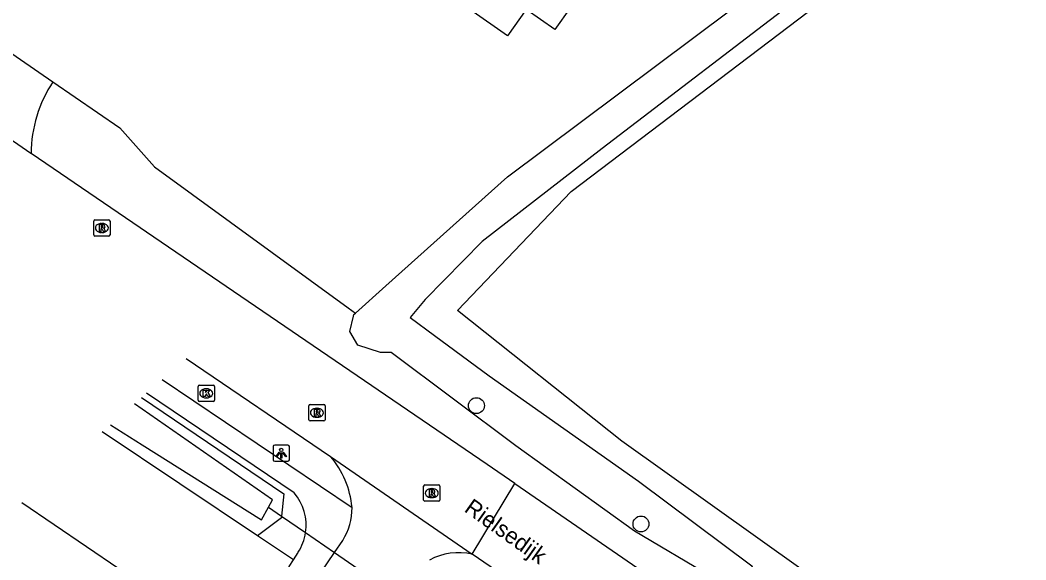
# Model space of a CAD drawing. Extents: x 163863 to 164644, y 379566 to 382155.
# Drawn here: x 164174.8 to 164236.6, y 381853.4 to 381886.6 of the extents above; entities that cross this region are included whole.
import ezdxf

# ---------------------------------------------------------------- set-up
doc = ezdxf.new("R2010")
doc.units = 0
for name, color, linetype in [('IMGEO_Boom', 7, 'Continuous'), ('IMGEO_Duiker', 7, 'Continuous'), ('IMGEO_Erf', 7, 'Continuous'), ('IMGEO_Grasland_overig', 7, 'Continuous'), ('IMGEO_Groenvoorziening', 7, 'Continuous'), ('IMGEO_Kolk', 7, 'Continuous'), ('IMGEO_Lichtpunt', 7, 'Continuous'), ('IMGEO_Openbare_ruimte_label', 7, 'Continuous'), ('IMGEO_Pand', 7, 'Continuous'), ('IMGEO_Rijbaan_lokaal_gesloten', 7, 'Continuous'), ('IMGEO_Rijbaan_lokaal_open', 7, 'Continuous'), ('IMGEO_Rioolput', 7, 'Continuous'), ('IMGEO_Voetpad_open', 7, 'Continuous'), ('IMGEO_Waterloop', 7, 'Continuous')]:
    doc.layers.add(name, color=color, linetype=linetype)

msp = doc.modelspace()

# ---------------------------------------------------------------- linework, layer by layer
at = {"layer": 'IMGEO_Boom'}
for centre in [(164202.821, 381862.893), (164212.934, 381855.62)]:
    msp.add_circle(centre, 0.489, dxfattribs=at)
at = {"layer": 'IMGEO_Duiker'}
msp.add_lwpolyline([(164190.042, 381856.658), (164190.846, 381856.104), (164192.323, 381855.089), (164194.104, 381853.864), (164197.871, 381851.272), (164199.409, 381850.214), (164201.216, 381848.971), (164201.883, 381848.512)], dxfattribs=at)
at = {"layer": 'IMGEO_Erf'}
msp.add_lwpolyline([(164189.365, 381854.902), (164179.829, 381861.277)], dxfattribs=at)
at = {"layer": 'IMGEO_Grasland_overig'}
msp.add_lwpolyline([(164335.006, 381775.051), (164322.428, 381783.408), (164286.005, 381809.753), (164256.457, 381829.627), (164222.906, 381852.769), (164211.763, 381860.7), (164201.663, 381868.745), (164208.654, 381876.058), (164252.396, 381909.265)], dxfattribs=at)
at = {"layer": 'IMGEO_Groenvoorziening'}
for points in [[(164176.8, 381882.795), (164180.902, 381879.968), (164183.031, 381877.576), (164194.945, 381868.909), (164195.394, 381868.583)], [(164182.231, 381863.385), (164190.987, 381857.475), (164190.846, 381856.104), (164190.836, 381856.002), (164189.365, 381854.902)], [(164191.58, 381853.421), (164189.365, 381854.902)]]:
    msp.add_lwpolyline(points, dxfattribs=at)
at = {"layer": 'IMGEO_Kolk'}
for p, q in [((164185.719, 381863.221), (164185.719, 381864.073)), ((164185.794, 381864.147), (164186.646, 381864.147)), ((164186.72, 381864.073), (164186.72, 381863.221)), ((164186.23, 381863.367), (164186.205, 381863.367)), ((164186.207, 381863.927), (164186.232, 381863.927)), ((164186.646, 381863.147), (164185.794, 381863.147))]:
    msp.add_line(p, q, dxfattribs=at)
for points in [[(164185.719, 381863.221), (164185.719, 381864.073)], [(164185.794, 381864.147), (164186.646, 381864.147)], [(164186.72, 381864.073), (164186.72, 381863.221)], [(164186.04, 381863.847), (164186.163, 381863.847), (164186.163, 381863.696), (164186.293, 381863.847), (164186.457, 381863.847), (164186.311, 381863.696), (164186.464, 381863.447), (164186.312, 381863.447), (164186.227, 381863.611), (164186.163, 381863.544), (164186.163, 381863.447), (164186.04, 381863.447), (164186.04, 381863.847)], [(164186.646, 381863.147), (164185.794, 381863.147)]]:
    msp.add_lwpolyline(points, dxfattribs=at)
for centre, start, end in [((164185.796, 381864.071), 91.55205, 178.44795), ((164185.796, 381864.071), 91.55205, 178.44795), ((164186.644, 381864.071), 1.55205, 88.44795), ((164186.644, 381864.071), 1.55205, 88.44795), ((164185.796, 381863.223), 181.55205, 268.44795), ((164185.796, 381863.223), 181.55205, 268.44795), ((164186.644, 381863.223), 271.55205, 358.44795), ((164186.644, 381863.223), 271.55205, 358.44795)]:
    msp.add_arc(centre, 0.0765, start, end, dxfattribs=at)
for centre, major_axis, ratio, start_param, end_param in [((164186.206, 381863.647), (-0.387, 0.002), 0.722429, 4.712389, 7.853982), ((164186.231, 381863.647), (-0.39, 0.002), 0.717154, 1.570796, 4.712389)]:
    msp.add_ellipse(centre, major_axis=major_axis, ratio=ratio, start_param=start_param, end_param=end_param, dxfattribs=at)
at = {"layer": 'IMGEO_Lichtpunt'}
for p, q in [((164190.331, 381860.374), (164190.331, 381859.567)), ((164190.331, 381860.374), (164190.331, 381859.567)), ((164191.233, 381860.469), (164190.425, 381860.469)), ((164191.233, 381860.469), (164190.425, 381860.469)), ((164191.327, 381859.567), (164191.327, 381860.374)), ((164191.327, 381859.567), (164191.327, 381860.374)), ((164190.425, 381859.473), (164191.233, 381859.473)), ((164190.425, 381859.473), (164191.233, 381859.473))]:
    msp.add_line(p, q, dxfattribs=at)
for points in [[(164190.705, 381860.038), (164190.744, 381860.01), (164190.556, 381859.748), (164190.518, 381859.775), (164190.705, 381860.038)], [(164190.807, 381859.99), (164190.854, 381859.99), (164190.854, 381859.668), (164190.807, 381859.668), (164190.807, 381859.99)], [(164190.917, 381860.01), (164190.955, 381860.037), (164191.142, 381859.775), (164191.103, 381859.747), (164190.917, 381860.01)]]:
    msp.add_lwpolyline(points, dxfattribs=at)
msp.add_circle((164190.83, 381860.172), 0.0994, dxfattribs=at)
for centre, start, end in [((164190.425, 381860.374), 90, 180), ((164190.425, 381860.374), 90, 180), ((164191.233, 381860.374), 0, 90), ((164191.233, 381860.374), 0, 90), ((164190.425, 381859.567), 180, 270), ((164190.425, 381859.567), 180, 270), ((164191.233, 381859.567), 270, 0), ((164191.233, 381859.567), 270, 360)]:
    msp.add_arc(centre, 0.0946, start, end, dxfattribs=at)
at = {"layer": 'IMGEO_Pand'}
for points in [[(164212.28, 381892.593), (164210.522, 381890.091), (164207.647, 381886), (164205.881, 381887.241), (164204.735, 381885.611), (164198.195, 381890.205), (164199.337, 381891.829), (164194.385, 381895.308), (164197.26, 381899.4), (164199.022, 381901.908), (164201.324, 381900.291), (164203.411, 381898.824), (164212.28, 381892.593)], [(164174.878, 381856.933), (164182.827, 381851.535), (164178.088, 381844.548), (164177.173, 381845.157), (164173.526, 381839.8), (164167.892, 381843.609), (164171.538, 381849.002), (164168.319, 381851.178)]]:
    msp.add_lwpolyline(points, dxfattribs=at)
at = {"layer": 'IMGEO_Rijbaan_lokaal_gesloten'}
for points in [[(164175.458, 381878.387), (164175.446, 381878.395), (164166.649, 381884.443), (164166.499, 381884.544)], [(164205.181, 381858.114), (164203.483, 381859.285), (164175.458, 381878.387)], [(164184.975, 381865.791), (164193.85, 381859.772)], [(164193.85, 381859.772), (164202.562, 381853.773)], [(164202.562, 381853.773), (164205.181, 381858.114)], [(164205.181, 381858.114), (164214.31, 381851.815)], [(164213.948, 381845.959), (164202.562, 381853.773)]]:
    msp.add_lwpolyline(points, dxfattribs=at)
at = {"layer": 'IMGEO_Rijbaan_lokaal_open'}
msp.add_lwpolyline([(164192.817, 381851.959), (164194.104, 381853.864), (164194.609, 381854.612)], dxfattribs=at)
for centre, radius, start, end in [((164189.621, 381856.131), 5.58, 5.22966, 40.72522), ((164191.427, 381856.599), 3.752, 328.02444, 0.6303), ((164201.76, 381849.906), 3.949, 78.28872, 117.56243)]:
    msp.add_arc(centre, radius, start, end, dxfattribs=at)
at = {"layer": 'IMGEO_Rioolput'}
for p, q in [((164179.304, 381873.386), (164179.304, 381874.238)), ((164179.379, 381874.312), (164180.231, 381874.312)), ((164179.792, 381874.092), (164179.817, 381874.092)), ((164180.305, 381874.238), (164180.305, 381873.386)), ((164180.231, 381873.312), (164179.379, 381873.312)), ((164179.815, 381873.532), (164179.79, 381873.532)), ((164192.521, 381862.03), (164192.521, 381862.882)), ((164192.596, 381862.956), (164193.448, 381862.956)), ((164193.009, 381862.736), (164193.034, 381862.736)), ((164193.522, 381862.882), (164193.522, 381862.03)), ((164193.032, 381862.176), (164193.007, 381862.176)), ((164193.448, 381861.956), (164192.596, 381861.956)), ((164199.579, 381857.093), (164199.579, 381857.945)), ((164199.654, 381858.019), (164200.506, 381858.019)), ((164200.067, 381857.799), (164200.092, 381857.799)), ((164200.58, 381857.945), (164200.58, 381857.093)), ((164200.09, 381857.239), (164200.065, 381857.239)), ((164200.506, 381857.019), (164199.654, 381857.019))]:
    msp.add_line(p, q, dxfattribs=at)
for points in [[(164179.304, 381873.386), (164179.304, 381874.238)], [(164179.379, 381874.312), (164180.231, 381874.312)], [(164179.893, 381874.01), (164179.641, 381874.012), (164179.641, 381873.612)], [(164179.819, 381873.931), (164179.765, 381873.931), (164179.765, 381873.85)], [(164179.765, 381873.85), (164179.817, 381873.85)], [(164180.305, 381874.238), (164180.305, 381873.386)], [(164180.231, 381873.312), (164179.379, 381873.312)], [(164179.641, 381873.612), (164179.765, 381873.612), (164179.765, 381873.774), (164179.776, 381873.774)], [(164179.823, 381873.745), (164179.894, 381873.612), (164180.034, 381873.612), (164179.969, 381873.738)], [(164192.521, 381862.03), (164192.521, 381862.882)], [(164192.596, 381862.956), (164193.448, 381862.956)], [(164193.522, 381862.882), (164193.522, 381862.03)], [(164193.11, 381862.654), (164192.858, 381862.656), (164192.858, 381862.256)], [(164192.858, 381862.256), (164192.982, 381862.256), (164192.982, 381862.418), (164192.993, 381862.418)], [(164193.036, 381862.575), (164192.982, 381862.575), (164192.982, 381862.494)], [(164192.982, 381862.494), (164193.034, 381862.494)], [(164193.04, 381862.389), (164193.111, 381862.256), (164193.251, 381862.256), (164193.186, 381862.382)], [(164193.448, 381861.956), (164192.596, 381861.956)], [(164199.579, 381857.093), (164199.579, 381857.945)], [(164199.654, 381858.019), (164200.506, 381858.019)], [(164200.58, 381857.945), (164200.58, 381857.093)], [(164200.168, 381857.717), (164199.916, 381857.719), (164199.916, 381857.319)], [(164199.916, 381857.319), (164200.04, 381857.319), (164200.04, 381857.481), (164200.051, 381857.481)], [(164200.094, 381857.638), (164200.04, 381857.638), (164200.04, 381857.557)], [(164200.04, 381857.557), (164200.092, 381857.557)], [(164200.098, 381857.452), (164200.169, 381857.319), (164200.309, 381857.319), (164200.244, 381857.445)], [(164200.506, 381857.019), (164199.654, 381857.019)]]:
    msp.add_lwpolyline(points, dxfattribs=at)
for centre, radius, start, end in [((164179.381, 381874.236), 0.0765, 91.55205, 178.44795), ((164179.381, 381874.236), 0.0765, 91.55205, 178.44795), ((164179.801, 381874.039), 0.19, 274.7715, 282.96867), ((164179.825, 381873.835), 0.0964, 77.00612, 93.18647), ((164179.839, 381873.892), 0.0378, 276.66336, 79.67722), ((164179.892, 381873.9), 0.109, 350.36119, 89.41601), ((164179.89, 381873.9), 0.112, 277.58423, 350.98172), ((164180.229, 381874.236), 0.0765, 1.55205, 88.44795), ((164180.229, 381874.236), 0.0765, 1.55205, 88.44795), ((164179.381, 381873.388), 0.0765, 181.55205, 268.44795), ((164179.381, 381873.388), 0.0765, 181.55205, 268.44795), ((164179.775, 381873.721), 0.0533, 26.02933, 88.69889), ((164179.874, 381873.685), 0.108, 29.51342, 73.79051), ((164180.229, 381873.388), 0.0765, 271.55205, 358.44795), ((164180.229, 381873.388), 0.0765, 271.55205, 358.44795), ((164192.598, 381862.88), 0.0765, 91.55205, 178.44795), ((164192.598, 381862.88), 0.0765, 91.55205, 178.44795), ((164193.446, 381862.88), 0.0765, 1.55205, 88.44795), ((164193.446, 381862.88), 0.0765, 1.55205, 88.44795), ((164192.992, 381862.365), 0.0533, 26.02933, 88.69889), ((164193.018, 381862.683), 0.19, 274.7715, 282.96867), ((164193.042, 381862.479), 0.0964, 77.00612, 93.18647), ((164193.056, 381862.536), 0.0378, 276.66336, 79.67722), ((164193.109, 381862.544), 0.109, 350.36119, 89.41601), ((164193.107, 381862.544), 0.112, 277.58423, 350.98172), ((164193.091, 381862.329), 0.108, 29.51342, 73.79051), ((164192.598, 381862.032), 0.0765, 181.55205, 268.44795), ((164192.598, 381862.032), 0.0765, 181.55205, 268.44795), ((164193.446, 381862.032), 0.0765, 271.55205, 358.44795), ((164193.446, 381862.032), 0.0765, 271.55205, 358.44795), ((164199.656, 381857.943), 0.0765, 91.55205, 178.44795), ((164199.656, 381857.943), 0.0765, 91.55205, 178.44795), ((164200.504, 381857.943), 0.0765, 1.55205, 88.44795), ((164200.504, 381857.943), 0.0765, 1.55205, 88.44795), ((164200.05, 381857.428), 0.0533, 26.02933, 88.69889), ((164200.076, 381857.746), 0.19, 274.7715, 282.96867), ((164200.1, 381857.542), 0.0964, 77.00612, 93.18647), ((164200.114, 381857.599), 0.0378, 276.66336, 79.67722), ((164200.167, 381857.607), 0.109, 350.36119, 89.41601), ((164200.165, 381857.607), 0.112, 277.58423, 350.98172), ((164200.149, 381857.392), 0.108, 29.51342, 73.79051), ((164199.656, 381857.095), 0.0765, 181.55205, 268.44795), ((164199.656, 381857.095), 0.0765, 181.55205, 268.44795), ((164200.504, 381857.095), 0.0765, 271.55205, 358.44795), ((164200.504, 381857.095), 0.0765, 271.55205, 358.44795)]:
    msp.add_arc(centre, radius, start, end, dxfattribs=at)
for centre, major_axis, ratio, start_param, end_param in [((164179.791, 381873.812), (-0.387, 0.002), 0.722429, 4.712389, 7.853982), ((164179.816, 381873.812), (-0.39, 0.002), 0.717154, 1.570796, 4.712389), ((164193.008, 381862.456), (-0.387, 0.002), 0.722429, 4.712389, 7.853982), ((164193.033, 381862.456), (-0.39, 0.002), 0.717154, 1.570796, 4.712389), ((164200.066, 381857.519), (-0.387, 0.002), 0.722429, 4.712389, 7.853982), ((164200.091, 381857.519), (-0.39, 0.002), 0.717154, 1.570796, 4.712389)]:
    msp.add_ellipse(centre, major_axis=major_axis, ratio=ratio, start_param=start_param, end_param=end_param, dxfattribs=at)
at = {"layer": 'IMGEO_Voetpad_open'}
for points in [[(164170.551, 381887.103), (164176.8, 381882.795)], [(164183.51, 381864.507), (164195.178, 381856.64)], [(164191.631, 381857.534), (164182.548, 381863.663)], [(164191.58, 381853.421), (164191.868, 381853.878)], [(164191.306, 381852.987), (164191.32, 381853.008), (164191.58, 381853.421)]]:
    msp.add_lwpolyline(points, dxfattribs=at)
for centre, radius, start, end in [((164183.44, 381878.365), 7.982, 146.29071, 179.84392), ((164189.269, 381855.545), 3.088, 351.50378, 40.10206), ((164189.29, 381855.538), 3.066, 327.23045, 351.58489)]:
    msp.add_arc(centre, radius, start, end, dxfattribs=at)
at = {"layer": 'IMGEO_Waterloop'}
for points in [[(164195.394, 381868.583), (164197.248, 381870.262), (164204.736, 381876.958), (164229.912, 381895.792), (164270.687, 381927.48), (164301.861, 381952.134), (164302.429, 381952.58)], [(164255.409, 381913.055), (164247.863, 381907.224), (164235.639, 381897.964), (164222.992, 381888.227), (164210.557, 381878.702), (164203.175, 381872.987), (164199.682, 381869.415), (164198.747, 381868.31), (164200.241, 381867.209), (164203.607, 381864.729), (164212.773, 381858.254), (164219.743, 381853.042), (164219.769, 381853.023)], [(164219.769, 381853.023), (164219.553, 381852.482), (164219.129, 381851.953), (164218.468, 381851.741), (164217.304, 381852.35), (164212.541, 381855.181), (164205.239, 381860.42), (164197.592, 381866.161), (164196.931, 381866.161), (164195.529, 381866.611), (164195.052, 381867.457), (164195.268, 381868.391), (164195.29, 381868.489), (164195.394, 381868.583)], [(164180.331, 381861.717), (164180.331, 381861.717), (164182.291, 381860.481), (164189.609, 381855.885), (164190.042, 381856.658), (164190.296, 381857.112), (164181.808, 381863.014)]]:
    msp.add_lwpolyline(points, dxfattribs=at)

# ---------------------------------------------------------------- texts
at = {"layer": 'IMGEO_Openbare_ruimte_label'}
msp.add_text('Rielsedijk', height=1, rotation=324.60889, dxfattribs=at).set_placement((164202.012, 381856.426))

doc.saveas('drawing.dxf')
